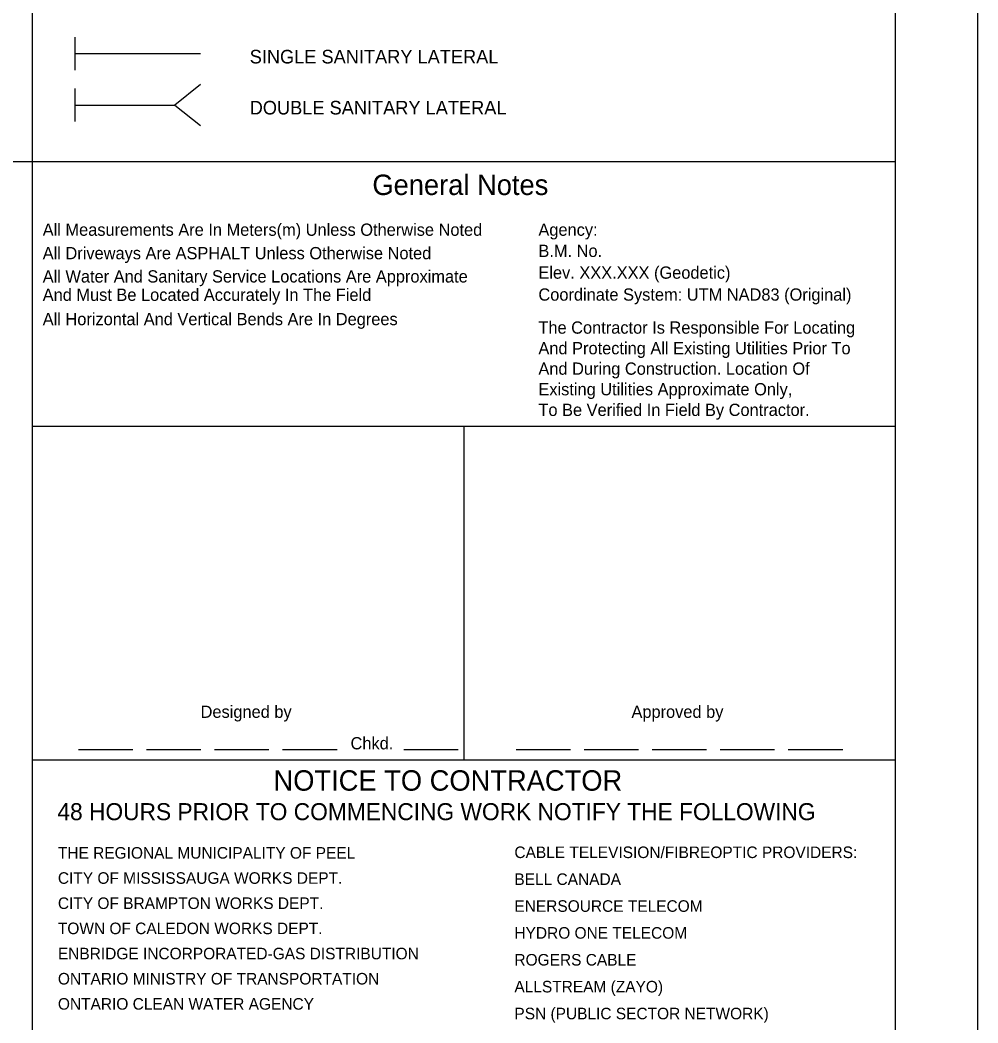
# Model space of a CAD drawing. Extents: x 613360 to 613780, y 4825621 to 4825911.
# Drawn here: x 613709.9 to 613780.3, y 4825692.8 to 4825766.5 of the extents above; entities that cross this region are included whole.
import ezdxf

# ---------------------------------------------------------------- set-up
doc = ezdxf.new("R2010")
doc.units = 0
for name, color, linetype in [('G-ANNO-LEGN', 7, 'Continuous'), ('G-ANNO-STMP', 7, 'Continuous'), ('G-ANNO-TEXT', 7, 'Continuous'), ('G-TTLB-OTLN', 7, 'Continuous'), ('G-TTLB-OTLN-PB', 7, 'Continuous')]:
    doc.layers.add(name, color=color, linetype=linetype)

msp = doc.modelspace()

# ---------------------------------------------------------------- linework, layer by layer
at = {"layer": 'G-ANNO-LEGN'}
for p, q in [((613713.885, 4825765.242), (613713.885, 4825762.813)), ((613713.885, 4825764.028), (613723.135, 4825764.028)), ((613713.885, 4825761.457), (613713.885, 4825759.028)), ((613713.885, 4825760.243), (613721.247, 4825760.243))]:
    msp.add_line(p, q, dxfattribs=at)
msp.add_lwpolyline([(613723.135, 4825761.747), (613721.247, 4825760.243), (613723.135, 4825758.742)], dxfattribs=at)
at = {"layer": 'G-ANNO-STMP'}
for p, q in [((613714.165, 4825712.893), (613718.165, 4825712.892)), ((613719.165, 4825712.892), (613723.165, 4825712.892)), ((613724.165, 4825712.892), (613728.165, 4825712.892)), ((613729.165, 4825712.892), (613733.165, 4825712.892)), ((613738.073, 4825712.892), (613742.073, 4825712.892)), ((613746.328, 4825712.892), (613750.328, 4825712.892)), ((613751.328, 4825712.892), (613755.328, 4825712.892)), ((613756.328, 4825712.892), (613760.328, 4825712.892)), ((613761.328, 4825712.892), (613765.328, 4825712.892)), ((613766.328, 4825712.892), (613770.328, 4825712.892))]:
    msp.add_line(p, q, dxfattribs=at)
at = {"layer": 'G-TTLB-OTLN'}
for p, q in [((613710.777, 4825623.508), (613710.777, 4825815.929)), ((613380.085, 4825756.108), (613774.178, 4825756.108)), ((613774.178, 4825736.624), (613710.777, 4825736.624)), ((613742.478, 4825736.624), (613742.478, 4825712.108)), ((613774.178, 4825712.108), (613710.777, 4825712.108))]:
    msp.add_line(p, q, dxfattribs=at)
msp.add_lwpolyline([(613380.085, 4825892.077), (613774.178, 4825892.077), (613774.178, 4825623.508), (613380.085, 4825623.508)], close=True, dxfattribs=at)
at = {"layer": 'G-TTLB-OTLN-PB'}
msp.add_lwpolyline([(613359.578, 4825620.908), (613780.27, 4825620.908), (613780.27, 4825894.677), (613359.578, 4825894.677)], close=True, dxfattribs=at)

# ---------------------------------------------------------------- texts
at = {"layer": 'G-ANNO-LEGN'}
for s, p in [('SINGLE SANITARY LATERAL  ', (613726.747, 4825763.304)), ('DOUBLE SANITARY LATERAL  ', (613726.747, 4825759.554))]:
    msp.add_text(s, height=1, dxfattribs=at).set_placement(p)
at = {"layer": 'G-ANNO-STMP'}
for s, p in [('Designed by', (613723.139, 4825715.207)), ('Approved by', (613754.806, 4825715.207)), ('Chkd.', (613734.158, 4825712.892))]:
    msp.add_text(s, height=0.9, dxfattribs=at).set_placement(p)
at = {"layer": 'G-ANNO-TEXT'}
for s, height, p in [('General Notes', 1.5, (613735.763, 4825753.635)), ('All Measurements Are In Meters(m) Unless Otherwise Noted', 0.9, (613711.535, 4825750.637)), ('All Driveways Are ASPHALT Unless Otherwise Noted', 0.9, (613711.535, 4825748.914)), ('All Water And Sanitary Service Locations Are Approximate', 0.9, (613711.535, 4825747.204)), ('And Must Be Located Accurately In The Field ', 0.9, (613711.535, 4825745.854)), ('All Horizontal And Vertical Bends Are In Degrees', 0.9, (613711.535, 4825744.067))]:
    msp.add_text(s, height=height, rotation=360, dxfattribs=at).set_placement(p)
for s, height, p in [('Agency: ', 0.9, (613747.967, 4825750.637)), ('B.M. No. ', 0.9, (613747.967, 4825749.084)), ('Elev. XXX.XXX (Geodetic)', 0.9, (613747.967, 4825747.484)), ('Coordinate System: UTM NAD83 (Original)', 0.9, (613747.967, 4825745.87)), ('The Contractor Is Responsible For Locating ', 0.9, (613747.967, 4825743.443)), ('And Protecting All Existing Utilities Prior To ', 0.9, (613747.967, 4825741.927)), ('And During Construction. Location Of ', 0.9, (613747.967, 4825740.427)), ('Existing Utilities Approximate Only, ', 0.9, (613747.967, 4825738.911)), ('To Be Verified In Field By Contractor.', 0.9, (613747.967, 4825737.396)), ('NOTICE TO CONTRACTOR', 1.5, (613728.497, 4825709.856)), ('48 HOURS PRIOR TO COMMENCING WORK NOTIFY THE FOLLOWING', 1.25, (613712.613, 4825707.688)), ('THE REGIONAL MUNICIPALITY OF PEEL', 0.85, (613712.651, 4825704.86)), ('CABLE TELEVISION/FIBREOPTIC PROVIDERS:', 0.85, (613746.202, 4825704.902)), ('CITY OF MISSISSAUGA WORKS DEPT.', 0.85, (613712.651, 4825703.01)), ('BELL CANADA', 0.85, (613746.202, 4825702.927)), ('CITY OF BRAMPTON WORKS DEPT.', 0.85, (613712.651, 4825701.16)), ('ENERSOURCE TELECOM', 0.85, (613746.202, 4825700.952)), ('TOWN OF CALEDON WORKS DEPT.', 0.85, (613712.651, 4825699.31)), ('HYDRO ONE TELECOM', 0.85, (613746.202, 4825698.977)), ('ENBRIDGE INCORPORATED-GAS DISTRIBUTION', 0.85, (613712.651, 4825697.46)), ('ROGERS CABLE', 0.85, (613746.202, 4825697.002)), ('ONTARIO MINISTRY OF TRANSPORTATION', 0.85, (613712.651, 4825695.61)), ('ALLSTREAM (ZAYO)', 0.85, (613746.202, 4825695.027)), ('ONTARIO CLEAN WATER AGENCY', 0.85, (613712.651, 4825693.76)), ('PSN (PUBLIC SECTOR NETWORK)', 0.85, (613746.202, 4825693.052))]:
    msp.add_text(s, height=height, dxfattribs=at).set_placement(p)

doc.saveas('drawing.dxf')
